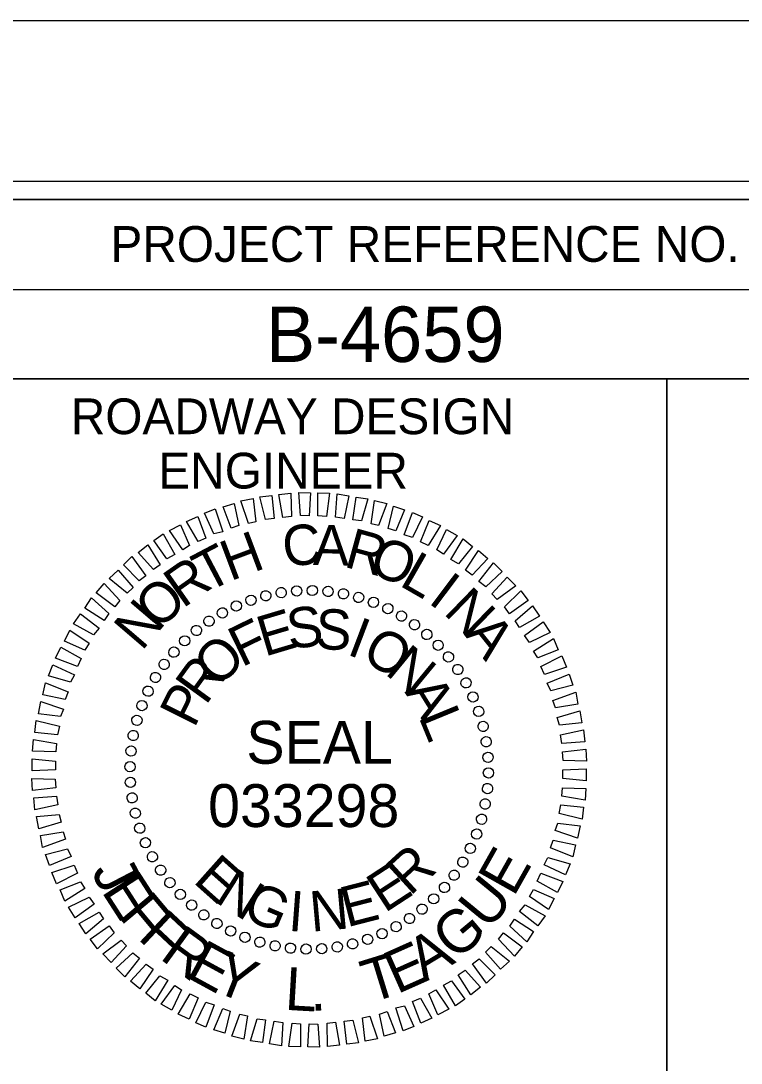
# Model space of a CAD drawing. Extents: x 574125 to 576234, y -56630 to -55530.
# Drawn here: x 575816.4 to 575917.2, y -55675.6 to -55529.8 of the extents above; entities that cross this region are included whole.
import ezdxf

# ---------------------------------------------------------------- set-up
doc = ezdxf.new("R2010")
doc.units = 0
for name, color, linetype in [('Sheet Data Field CELL', 7, 'Continuous'), ('Sheet Plot Border Inside CELL', 7, 'Continuous'), ('Sheet Plot Border Outside CELL', 7, 'Continuous'), ('Sheet Professional Seal CELL', 7, 'Continuous'), ('Sheet Profile CELL', 7, 'Continuous'), ('Sheet Profile Grid Major CELL', 7, 'Continuous')]:
    doc.layers.add(name, color=color, linetype=linetype)

msp = doc.modelspace()

# ---------------------------------------------------------------- linework, layer by layer
at = {"layer": 'Sheet Plot Border Inside CELL'}
msp.add_lwpolyline([(576019.31, -55552.3), (574352.81, -55552.3), (574352.81, -56607.4), (576019.31, -56607.4)], close=True, dxfattribs=at)
at = {"layer": 'Sheet Plot Border Outside CELL'}
msp.add_lwpolyline([(576023.81, -55529.85), (574339.81, -55529.85), (574339.81, -56629.85), (576023.81, -56629.85)], close=True, dxfattribs=at)
at = {"layer": 'Sheet Professional Seal CELL'}
for p, q in [((575850.67, -55610.24), (575850.67, -55610.24)), ((575852.87, -55609.84), (575852.87, -55609.84)), ((575855.02, -55609.54), (575855.02, -55609.54)), ((575857.22, -55609.49), (575857.22, -55609.49)), ((575859.42, -55609.64), (575859.42, -55609.64)), ((575861.57, -55609.99), (575861.57, -55609.99)), ((575846.57, -55611.64), (575846.57, -55611.64)), ((575848.57, -55610.84), (575848.57, -55610.84)), ((575863.67, -55610.44), (575863.67, -55610.44)), ((575865.77, -55611.14), (575865.77, -55611.14)), ((575844.62, -55612.64), (575844.62, -55612.64)), ((575867.77, -55612.04), (575867.77, -55612.04)), ((575869.72, -55613.04), (575869.72, -55613.04)), ((575842.72, -55613.79), (575842.72, -55613.79)), ((575871.52, -55614.29), (575871.52, -55614.29)), ((575840.97, -55615.04), (575840.97, -55615.04)), ((575873.27, -55615.64), (575873.27, -55615.64)), ((575839.32, -55616.54), (575839.32, -55616.54)), ((575874.82, -55617.14), (575874.82, -55617.14)), ((575837.82, -55618.09), (575837.82, -55618.09)), ((575876.32, -55618.79), (575876.32, -55618.79)), ((575836.47, -55619.84), (575836.47, -55619.84)), ((575877.57, -55620.54), (575877.57, -55620.54)), ((575835.22, -55621.64), (575835.22, -55621.64)), ((575878.72, -55622.44), (575878.72, -55622.44)), ((575834.22, -55623.59), (575834.22, -55623.59)), ((575879.72, -55624.39), (575879.72, -55624.39)), ((575833.32, -55625.59), (575833.32, -55625.59)), ((575880.52, -55626.39), (575880.52, -55626.39)), ((575832.62, -55627.69), (575832.62, -55627.69)), ((575881.12, -55628.49), (575881.12, -55628.49)), ((575832.17, -55629.79), (575832.17, -55629.79)), ((575881.52, -55630.69), (575881.52, -55630.69)), ((575831.82, -55631.94), (575831.82, -55631.94)), ((575881.82, -55632.84), (575881.82, -55632.84)), ((575831.67, -55634.14), (575831.67, -55634.14)), ((575856.77, -55634.59), (575856.77, -55634.59)), ((575881.87, -55635.04), (575881.87, -55635.04)), ((575831.72, -55636.34), (575831.72, -55636.34)), ((575881.72, -55637.24), (575881.72, -55637.24)), ((575832.02, -55638.49), (575832.02, -55638.49)), ((575881.37, -55639.39), (575881.37, -55639.39)), ((575832.42, -55640.69), (575832.42, -55640.69)), ((575880.92, -55641.49), (575880.92, -55641.49)), ((575833.02, -55642.79), (575833.02, -55642.79)), ((575880.22, -55643.59), (575880.22, -55643.59)), ((575833.82, -55644.79), (575833.82, -55644.79)), ((575834.82, -55646.74), (575834.82, -55646.74)), ((575879.32, -55645.59), (575879.32, -55645.59)), ((575878.32, -55647.54), (575878.32, -55647.54)), ((575835.97, -55648.64), (575835.97, -55648.64)), ((575877.07, -55649.34), (575877.07, -55649.34)), ((575837.22, -55650.39), (575837.22, -55650.39)), ((575875.72, -55651.09), (575875.72, -55651.09)), ((575838.72, -55652.04), (575838.72, -55652.04)), ((575874.22, -55652.64), (575874.22, -55652.64)), ((575840.27, -55653.54), (575840.27, -55653.54)), ((575872.57, -55654.14), (575872.57, -55654.14)), ((575842.02, -55654.89), (575842.02, -55654.89)), ((575870.82, -55655.39), (575870.82, -55655.39)), ((575843.82, -55656.14), (575843.82, -55656.14)), ((575868.92, -55656.54), (575868.92, -55656.54)), ((575845.77, -55657.14), (575845.77, -55657.14)), ((575847.77, -55658.04), (575847.77, -55658.04)), ((575864.97, -55658.34), (575864.97, -55658.34)), ((575866.97, -55657.54), (575866.97, -55657.54)), ((575849.87, -55658.74), (575849.87, -55658.74)), ((575851.97, -55659.19), (575851.97, -55659.19)), ((575854.12, -55659.54), (575854.12, -55659.54)), ((575856.32, -55659.69), (575856.32, -55659.69)), ((575858.52, -55659.64), (575858.52, -55659.64)), ((575860.67, -55659.34), (575860.67, -55659.34)), ((575862.87, -55658.94), (575862.87, -55658.94))]:
    msp.add_line(p, q, dxfattribs=at)
for points in [[(575855.57, -55599.04), (575855.32, -55595.79), (575856.97, -55595.84), (575856.77, -55599.09)], [(575857.97, -55599.09), (575857.97, -55595.84), (575859.62, -55595.89), (575859.17, -55599.14)], [(575848.27, -55600.14), (575847.22, -55596.99), (575848.92, -55596.64), (575849.32, -55599.89)], [(575850.67, -55599.59), (575849.87, -55596.39), (575851.52, -55596.24), (575851.87, -55599.44)], [(575853.07, -55599.29), (575852.52, -55596.09), (575854.22, -55595.89), (575854.27, -55599.14)], [(575860.47, -55599.24), (575860.67, -55595.99), (575862.32, -55596.29), (575861.67, -55599.44)], [(575862.87, -55599.64), (575863.32, -55596.44), (575864.97, -55596.69), (575864.07, -55599.79)], [(575865.42, -55600.19), (575865.92, -55596.94), (575867.62, -55597.34), (575866.47, -55600.44)], [(575843.42, -55601.59), (575842.12, -55598.69), (575843.62, -55598.09), (575844.67, -55601.29)], [(575845.87, -55600.79), (575844.72, -55597.79), (575846.27, -55597.34), (575846.92, -55600.44)], [(575867.82, -55600.84), (575868.57, -55597.74), (575870.12, -55598.24), (575868.87, -55601.19)], [(575870.07, -55601.74), (575871.22, -55598.59), (575872.62, -55599.19), (575871.22, -55602.09)], [(575841.22, -55602.64), (575839.62, -55599.84), (575841.17, -55599.14), (575842.32, -55602.19)], [(575872.32, -55602.69), (575873.57, -55599.74), (575875.12, -55600.44), (575873.42, -55603.24)], [(575836.87, -55605.09), (575835.02, -55602.54), (575836.32, -55601.59), (575837.97, -55604.49)], [(575839.07, -55603.84), (575837.22, -55601.14), (575838.77, -55600.34), (575840.02, -55603.24)], [(575874.62, -55603.84), (575875.97, -55600.99), (575877.47, -55601.84), (575875.57, -55604.44)], [(575876.57, -55605.19), (575878.32, -55602.29), (575879.62, -55603.34), (575877.67, -55605.79)], [(575834.97, -55606.59), (575832.82, -55604.19), (575834.17, -55603.14), (575835.92, -55605.94)], [(575878.62, -55606.69), (575880.47, -55603.94), (575881.77, -55605.04), (575879.57, -55607.39)], [(575832.97, -55608.14), (575830.77, -55605.94), (575831.97, -55604.74), (575833.92, -55607.44)], [(575880.52, -55608.24), (575882.57, -55605.64), (575883.77, -55606.84), (575881.47, -55608.99)], [(575831.32, -55609.89), (575828.77, -55607.84), (575830.02, -55606.69), (575832.12, -55609.09)], [(575829.57, -55611.79), (575826.97, -55609.84), (575828.07, -55608.54), (575830.27, -55610.89)], [(575882.32, -55609.99), (575884.47, -55607.64), (575885.67, -55608.84), (575883.07, -55610.79)], [(575884.07, -55611.79), (575886.37, -55609.54), (575887.42, -55610.89), (575884.77, -55612.79)], [(575828.07, -55613.69), (575825.37, -55611.99), (575826.32, -55610.54), (575828.72, -55612.74)], [(575885.57, -55613.74), (575888.02, -55611.64), (575888.97, -55613.09), (575886.17, -55614.69)], [(575826.57, -55615.69), (575823.77, -55614.19), (575824.77, -55612.79), (575827.37, -55614.79)], [(575886.87, -55615.79), (575889.52, -55613.89), (575890.47, -55615.39), (575887.57, -55616.79)], [(575825.37, -55617.84), (575822.52, -55616.59), (575823.27, -55615.04), (575825.97, -55616.89)], [(575888.17, -55617.99), (575890.97, -55616.24), (575891.62, -55617.79), (575888.77, -55618.94)], [(575824.37, -55620.14), (575821.27, -55618.99), (575822.02, -55617.44), (575824.87, -55619.04)], [(575889.17, -55620.14), (575892.12, -55618.64), (575892.77, -55620.24), (575889.67, -55621.24)], [(575823.37, -55622.34), (575820.27, -55621.44), (575820.92, -55619.89), (575823.92, -55621.29)], [(575890.07, -55622.49), (575893.12, -55621.19), (575893.67, -55622.74), (575890.57, -55623.54)], [(575822.62, -55624.74), (575819.52, -55624.09), (575819.87, -55622.44), (575823.02, -55623.69)], [(575890.87, -55624.89), (575894.07, -55623.74), (575894.37, -55625.39), (575891.22, -55625.94)], [(575821.97, -55627.14), (575818.87, -55626.74), (575819.22, -55625.04), (575822.37, -55626.09)], [(575891.47, -55627.29), (575894.62, -55626.34), (575894.92, -55628.04), (575891.77, -55628.34)], [(575821.57, -55629.69), (575818.37, -55629.39), (575818.57, -55627.69), (575821.82, -55628.49)], [(575891.92, -55629.69), (575895.17, -55628.99), (575895.32, -55630.69), (575892.12, -55630.89)], [(575821.32, -55632.09), (575818.07, -55631.99), (575818.17, -55630.34), (575821.42, -55630.89)], [(575892.22, -55632.09), (575895.47, -55631.69), (575895.57, -55633.39), (575892.32, -55633.29)], [(575821.27, -55634.59), (575818.02, -55634.74), (575818.02, -55633.04), (575821.27, -55633.39)], [(575892.27, -55634.59), (575895.52, -55634.44), (575895.52, -55636.14), (575892.27, -55635.79)], [(575821.32, -55637.09), (575818.07, -55637.49), (575817.97, -55635.79), (575821.22, -55635.89)], [(575892.22, -55637.09), (575895.47, -55637.19), (575895.37, -55638.84), (575892.12, -55638.29)], [(575821.62, -55639.49), (575818.37, -55640.19), (575818.22, -55638.49), (575821.42, -55638.29)], [(575891.97, -55639.49), (575895.17, -55639.79), (575894.97, -55641.49), (575891.72, -55640.69)], [(575822.07, -55641.89), (575818.92, -55642.84), (575818.62, -55641.14), (575821.77, -55640.84)], [(575891.57, -55642.04), (575894.67, -55642.44), (575894.32, -55644.14), (575891.17, -55643.09)], [(575822.67, -55644.29), (575819.47, -55645.44), (575819.17, -55643.79), (575822.32, -55643.24)], [(575890.92, -55644.44), (575894.02, -55645.09), (575893.67, -55646.74), (575890.52, -55645.49)], [(575823.47, -55646.69), (575820.42, -55647.99), (575819.87, -55646.44), (575822.97, -55645.64)], [(575890.17, -55646.84), (575893.27, -55647.74), (575892.62, -55649.29), (575889.62, -55647.89)], [(575824.37, -55649.04), (575821.42, -55650.54), (575820.77, -55648.94), (575823.87, -55647.94)], [(575889.17, -55649.04), (575892.27, -55650.19), (575891.52, -55651.74), (575888.67, -55650.14)], [(575825.37, -55651.19), (575822.57, -55652.94), (575821.92, -55651.39), (575824.77, -55650.24)], [(575826.67, -55653.39), (575824.02, -55655.29), (575823.07, -55653.79), (575825.97, -55652.39)], [(575888.17, -55651.34), (575891.02, -55652.59), (575890.27, -55654.14), (575887.57, -55652.29)], [(575886.97, -55653.49), (575889.77, -55654.99), (575888.77, -55656.39), (575886.17, -55654.39)], [(575827.97, -55655.44), (575825.52, -55657.54), (575824.57, -55656.09), (575827.37, -55654.49)], [(575885.47, -55655.49), (575888.17, -55657.19), (575887.22, -55658.64), (575884.82, -55656.44)], [(575829.47, -55657.39), (575827.17, -55659.64), (575826.12, -55658.29), (575828.77, -55656.39)], [(575831.22, -55659.19), (575829.07, -55661.54), (575827.87, -55660.34), (575830.47, -55658.39)], [(575883.97, -55657.39), (575886.57, -55659.34), (575885.47, -55660.64), (575883.27, -55658.29)], [(575882.22, -55659.29), (575884.77, -55661.34), (575883.52, -55662.49), (575881.42, -55660.09)], [(575833.02, -55660.94), (575830.97, -55663.54), (575829.77, -55662.34), (575832.07, -55660.19)], [(575880.57, -55661.04), (575882.77, -55663.24), (575881.57, -55664.44), (575879.62, -55661.74)], [(575834.92, -55662.49), (575833.07, -55665.24), (575831.77, -55664.14), (575833.97, -55661.79)], [(575878.57, -55662.59), (575880.72, -55664.99), (575879.37, -55666.04), (575877.62, -55663.24)], [(575836.97, -55663.99), (575835.22, -55666.89), (575833.92, -55665.84), (575835.87, -55663.39)], [(575876.67, -55664.09), (575878.52, -55666.64), (575877.22, -55667.59), (575875.57, -55664.69)], [(575838.92, -55665.34), (575837.57, -55668.19), (575836.07, -55667.34), (575837.97, -55664.74)], [(575874.47, -55665.34), (575876.32, -55668.04), (575874.77, -55668.84), (575873.52, -55665.94)], [(575841.22, -55666.49), (575839.97, -55669.44), (575838.42, -55668.74), (575840.12, -55665.94)], [(575843.47, -55667.44), (575842.32, -55670.59), (575840.92, -55669.99), (575842.32, -55667.09)], [(575872.32, -55666.54), (575873.92, -55669.34), (575872.37, -55670.04), (575871.22, -55666.99)], [(575845.72, -55668.34), (575844.97, -55671.44), (575843.42, -55670.94), (575844.67, -55667.99)], [(575867.67, -55668.39), (575868.82, -55671.39), (575867.27, -55671.84), (575866.62, -55668.74)], [(575870.12, -55667.59), (575871.42, -55670.49), (575869.92, -55671.09), (575868.87, -55667.89)], [(575848.12, -55668.99), (575847.62, -55672.24), (575845.92, -55671.84), (575847.07, -55668.74)], [(575850.67, -55669.54), (575850.22, -55672.74), (575848.57, -55672.49), (575849.47, -55669.39)], [(575853.07, -55669.94), (575852.87, -55673.19), (575851.22, -55672.89), (575851.87, -55669.74)], [(575855.57, -55670.09), (575855.57, -55673.34), (575853.92, -55673.29), (575854.37, -55670.04)], [(575857.97, -55670.14), (575858.22, -55673.39), (575856.57, -55673.34), (575856.77, -55670.09)], [(575860.47, -55669.89), (575861.02, -55673.09), (575859.32, -55673.29), (575859.27, -55670.04)], [(575862.87, -55669.59), (575863.67, -55672.79), (575862.02, -55672.94), (575861.67, -55669.74)], [(575865.27, -55669.04), (575866.32, -55672.19), (575864.62, -55672.54), (575864.22, -55669.29)]]:
    msp.add_lwpolyline(points, close=True, dxfattribs=at)
for centre, major_axis in [((575855.02, -55609.57), (-0.05, 0.718)), ((575857.21, -55609.51), (0.013, 0.72)), ((575859.39, -55609.64), (0.075, 0.716)), ((575848.61, -55610.87), (-0.234, 0.681)), ((575850.71, -55610.25), (-0.174, 0.699)), ((575852.85, -55609.81), (-0.113, 0.711)), ((575861.56, -55609.97), (0.137, 0.707)), ((575863.69, -55610.48), (0.198, 0.692)), ((575865.76, -55611.17), (0.258, 0.672)), ((575844.61, -55612.65), (-0.349, 0.63)), ((575846.57, -55611.67), (-0.293, 0.658)), ((575867.77, -55612.04), (0.316, 0.647)), ((575842.75, -55613.79), (-0.403, 0.597)), ((575869.69, -55613.09), (0.371, 0.617)), ((575840.99, -55615.1), (-0.453, 0.56)), ((575871.51, -55614.3), (0.423, 0.582)), ((575839.35, -55616.55), (-0.5, 0.518)), ((575873.23, -55615.66), (0.472, 0.543)), ((575837.84, -55618.13), (-0.543, 0.472)), ((575874.81, -55617.16), (0.518, 0.5)), ((575836.48, -55619.84), (-0.582, 0.423)), ((575876.26, -55618.8), (0.56, 0.453)), ((575877.56, -55620.56), (0.597, 0.403)), ((575835.27, -55621.67), (-0.617, 0.371)), ((575878.71, -55622.43), (0.63, 0.349)), ((575834.23, -55623.59), (-0.647, 0.316)), ((575833.36, -55625.6), (-0.672, 0.258)), ((575879.68, -55624.39), (0.658, 0.293)), ((575880.49, -55626.42), (0.681, 0.234)), ((575832.66, -55627.67), (-0.692, 0.198)), ((575881.11, -55628.52), (0.699, 0.174)), ((575832.15, -55629.8), (-0.707, 0.137)), ((575881.54, -55630.66), (0.711, 0.113)), ((575831.83, -55631.96), (-0.716, 0.075)), ((575881.79, -55632.84), (0.718, 0.05)), ((575831.7, -55634.15), (-0.72, 0.013)), ((575881.85, -55635.02), (0.72, -0.013)), ((575831.75, -55636.34), (-0.718, -0.05)), ((575881.72, -55637.21), (0.716, -0.075)), ((575832, -55638.51), (-0.711, -0.113)), ((575881.39, -55639.37), (0.707, -0.137)), ((575832.44, -55640.65), (-0.699, -0.174)), ((575880.88, -55641.5), (0.692, -0.198)), ((575833.06, -55642.75), (-0.681, -0.234)), ((575880.19, -55643.57), (0.672, -0.258)), ((575833.86, -55644.79), (-0.658, -0.293)), ((575879.31, -55645.58), (0.647, -0.316)), ((575834.84, -55646.75), (-0.63, -0.349)), ((575878.27, -55647.5), (0.617, -0.371)), ((575835.98, -55648.61), (-0.597, -0.403)), ((575837.28, -55650.37), (-0.56, -0.453)), ((575877.06, -55649.33), (0.582, -0.423)), ((575838.73, -55652.01), (-0.518, -0.5)), ((575875.7, -55651.04), (0.543, -0.472)), ((575874.19, -55652.63), (0.5, -0.518)), ((575840.32, -55653.51), (-0.472, -0.543)), ((575842.03, -55654.88), (-0.423, -0.582)), ((575872.56, -55654.08), (0.453, -0.56)), ((575843.86, -55656.08), (-0.371, -0.617)), ((575870.8, -55655.38), (0.403, -0.597)), ((575845.78, -55657.13), (-0.316, -0.647)), ((575866.97, -55657.5), (0.293, -0.658)), ((575868.93, -55656.52), (0.349, -0.63)), ((575847.78, -55658), (-0.258, -0.672)), ((575849.86, -55658.69), (-0.198, -0.692)), ((575851.99, -55659.21), (-0.137, -0.707)), ((575862.84, -55658.92), (0.174, -0.699)), ((575864.94, -55658.3), (0.234, -0.681)), ((575854.15, -55659.53), (-0.075, -0.716)), ((575856.33, -55659.66), (-0.013, -0.72)), ((575858.52, -55659.61), (0.05, -0.718)), ((575860.7, -55659.36), (0.113, -0.711))]:
    msp.add_ellipse(centre, major_axis=major_axis, ratio=0.999708, dxfattribs=at)
at = {"layer": 'Sheet Profile CELL'}
for p, q in [((576023.81, -55529.85), (574339.81, -55529.85)), ((575806.76, -55567.4), (576006.81, -55567.4)), ((575906.81, -55579.9), (575906.81, -55692.35))]:
    msp.add_line(p, q, dxfattribs=at)
for points in [[(576006.81, -55554.85), (574506.81, -55554.85), (574506.81, -56604.85), (576006.81, -56604.85)], [(575806.76, -55554.85), (576006.81, -55554.85), (576006.81, -55579.9), (575806.76, -55579.9)], [(575806.76, -55579.9), (575906.81, -55579.9), (575906.81, -55692.4), (575806.76, -55692.4)], [(575906.81, -55579.9), (576006.81, -55579.9), (576006.81, -55692.4), (575906.81, -55692.4)]]:
    msp.add_lwpolyline(points, close=True, dxfattribs=at)
at = {"layer": 'Sheet Profile Grid Major CELL'}
msp.add_lwpolyline([(575806.81, -55554.85), (575833.11, -55554.85)], dxfattribs=at)

# ---------------------------------------------------------------- texts
at = {"layer": 'Sheet Data Field CELL'}
msp.add_text('B-4659', height=7.75, dxfattribs=at).set_placement((575850.69, -55577.55))
at = {"layer": 'Sheet Professional Seal CELL'}
for s, height, rotation, p in [('C', 5.64, 6.2199, (575853.32, -55606.24)), ('H', 5.64, 20.6195, (575845.72, -55608.24)), ('A', 5.64, 359.0203, (575857.27, -55605.94)), ('R', 5.64, 344.6211, (575861.47, -55606.14)), ('T', 5.64, 27.8198, (575842.47, -55609.89)), ('O', 5.64, 337.4212, (575864.82, -55606.89)), ('L', 5.64, 330.2209, (575869.22, -55608.74)), ('R', 5.64, 35.0205, (575839.07, -55612.09)), ('I', 5.64, 323.0201, (575873.27, -55611.14)), ('O', 5.64, 42.2217, (575835.62, -55615.19)), ('N', 5.64, 315.8189, (575875.42, -55612.69)), ('N', 5.64, 49.4235, (575833.32, -55618.09)), ('S', 5.64, 7.2556, (575853.97, -55617.74)), ('F', 5.64, 25.967, (575847.32, -55620.29)), ('E', 5.64, 16.6111, (575850.52, -55618.79)), ('S', 5.64, 357.9004, (575857.57, -55617.69)), ('I', 5.64, 339.1896, (575861.87, -55618.39)), ('A', 5.64, 308.6172, (575878.37, -55615.64)), ('O', 5.64, 44.6812, (575844.02, -55623.24)), ('O', 5.64, 329.8335, (575863.87, -55619.09)), ('N', 5.64, 320.4766, (575867.22, -55621.09)), ('R', 5.64, 54.0397, (575842.27, -55625.69)), ('P', 5.64, 63.3989, (575840.67, -55628.89)), ('A', 5.64, 301.7603, (575870.07, -55623.69)), ('L', 5.64, 292.4009, (575872.02, -55627.14)), ('SEAL', 5.998, 360, (575847.97, -55633.74)), ('E', 6, 60.587, (575885.37, -55652.48)), ('E', 5.64, 318.2769, (575840.37, -55650.24)), ('R', 5.64, 42.4814, (575870.87, -55652.34)), ('J', 6, 297.5615, (575826.18, -55648.81)), ('E', 5.64, 33.1241, (575867.32, -55654.69)), ('E', 6, 302.8193, (575827.61, -55651.55)), ('N', 5.64, 327.634, (575843.37, -55652.94)), ('U', 6, 50.6494, (575881.85, -55657.15)), ('G', 5.64, 336.9902, (575847.17, -55655.19)), ('N', 5.64, 5.0564, (575857.07, -55657.24)), ('E', 5.64, 14.4118, (575862.02, -55656.64)), ('F', 6, 309.9286, (575829.94, -55655.03)), ('I', 5.64, 355.7012, (575853.72, -55657.09)), ('G', 6, 39.9236, (575877.21, -55661.42)), ('F', 6, 316.9452, (575832.64, -55658.16)), ('R', 6, 323.9618, (575835.7, -55660.93)), ('E', 6, 331.4421, (575839.3, -55663.45)), ('A', 6, 31.0833, (575872.85, -55664.25)), ('Y', 6, 338.5514, (575843.01, -55665.39)), ('E', 6, 23.9739, (575869.05, -55666.01)), ('T', 6, 17.1737, (575865.25, -55667.24)), ('L', 6, 356.6648, (575853.27, -55668.14)), ('.', 6, 2.9396, (575856.96, -55668.32))]:
    msp.add_text(s, height=height, rotation=rotation, dxfattribs=at).set_placement(p)
msp.add_text('033298', height=5.998, dxfattribs=at).set_placement((575842.62, -55642.59))
at = {"layer": 'Sheet Profile CELL'}
for s, height, p in [('PROJECT REFERENCE NO.', 5.0001, (575828.96, -55563.55)), ('ROADWAY DESIGN', 5.0001, (575823.41, -55587.65)), ('ENGINEER', 5, (575835.66, -55595.25))]:
    msp.add_text(s, height=height, rotation=360, dxfattribs=at).set_placement(p)

doc.saveas('drawing.dxf')
